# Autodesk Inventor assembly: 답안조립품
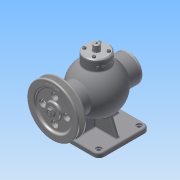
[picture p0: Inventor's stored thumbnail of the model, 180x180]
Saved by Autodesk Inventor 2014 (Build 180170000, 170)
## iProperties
Created: 2017-01
Part Number: 답안조립품
Document SubType Name: Assembly
Designer: ksu
Author: ksu
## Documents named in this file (19)
- C:\Users\ksu\Desktop\470118V1013\답안조립품.iam
- C:\Users\ksu\Desktop\470118V1013\본체.ipt
- C:\Users\ksu\Desktop\470118V1013\470118V1013\V-벨트풀리.ipt
- C:\Users\ksu\Desktop\470118V1013\470118V1013\너트 M8.ipt
- C:\Users\ksu\Desktop\470118V1013\470118V1013\뒤커버.ipt
- C:\Users\ksu\Desktop\470118V1013\470118V1013\멈춤링- 15 x 1.ipt
- C:\Users\ksu\Desktop\470118V1013\470118V1013\멈춤링- 35x1.6.ipt
- KS B 1336 - 35x1.6.ipt
- C:\Users\ksu\Desktop\470118V1013\470118V1013\베어링- 6202.ipt
- KS B 2023 - 6202 - 15 x 35 x 11 - 7.8.ipt
- C:\Users\ksu\Desktop\470118V1013\470118V1013\볼트 M4 x 12.ipt
- C:\Users\ksu\Desktop\470118V1013\470118V1013\볼트 M4 x 16.ipt
- C:\Users\ksu\Desktop\470118V1013\470118V1013\부시.ipt
- C:\Users\ksu\Desktop\470118V1013\470118V1013\상부커버.ipt
- C:\Users\ksu\Desktop\470118V1013\470118V1013\슬라이드.ipt
- C:\Users\ksu\Desktop\470118V1013\470118V1013\앞커버.ipt
- C:\Users\ksu\Desktop\470118V1013\470118V1013\오일실 15 30 7.ipt
- C:\Users\ksu\Desktop\470118V1013\470118V1013\키 4 x 4 x 12.ipt
- C:\Users\ksu\Desktop\470118V1013\470118V1013\편심축.ipt
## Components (16 placed, 5 different names)
1. V-벨트풀리:1 — Mate:10, Mate:11, Mate:12
2. KS B 1336 - 35x1.6:1 — Mate:21, Mate:22
3. KS B 2023 - 6202 - 15 x 35 x 11 - 7.8:1 — Mate:3, Mate:4, Mate:6
4. KS B 2023 - 6202 - 15 x 35 x 11 - 7.8:2 — Mate:21, Mate:22, Mate:23, Mate:24, Mate:25, Mate:26, Mate:27
5. ISO 4762 M4 x 16:1 — Mate:19, Mate:20
6. ISO 4762 M4 x 16:2
7. ISO 4762 M4 x 16:3
8. ISO 4762 M4 x 16:4
9. ISO 4762 M4 x 16:5 — Mate:29, Mate:30
10. ISO 4762 M4 x 16:6
11. ISO 4762 M4 x 16:7
12. ISO 4762 M4 x 16:8
13. KS B 1021 - 에 따름 ISO 1207 - 미터 A  M 4 x 12:1 — Mate:33, Mate:34
14. KS B 1021 - 에 따름 ISO 1207 - 미터 A  M 4 x 12:2
15. KS B 1021 - 에 따름 ISO 1207 - 미터 A  M 4 x 12:3
16. KS B 1021 - 에 따름 ISO 1207 - 미터 A  M 4 x 12:4
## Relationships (19: Mate 19)
- Mate:3: KS B 2023 - 6202 - 15 x 35 x 11 - 7.8:1
- Mate:4: KS B 2023 - 6202 - 15 x 35 x 11 - 7.8:1
- Mate:6: KS B 2023 - 6202 - 15 x 35 x 11 - 7.8:1
- Mate:10: V-벨트풀리:1
- Mate:11: V-벨트풀리:1
- Mate:12: V-벨트풀리:1
- Mate:19: ISO 4762 M4 x 16:1
- Mate:20: ISO 4762 M4 x 16:1
- Mate:21: KS B 1336 - 35x1.6:1 ↔ KS B 2023 - 6202 - 15 x 35 x 11 - 7.8:2
- Mate:22: KS B 1336 - 35x1.6:1 ↔ KS B 2023 - 6202 - 15 x 35 x 11 - 7.8:2
- Mate:23: KS B 2023 - 6202 - 15 x 35 x 11 - 7.8:2
- Mate:24: KS B 2023 - 6202 - 15 x 35 x 11 - 7.8:2
- Mate:25: KS B 2023 - 6202 - 15 x 35 x 11 - 7.8:2
- Mate:26: KS B 2023 - 6202 - 15 x 35 x 11 - 7.8:2
- Mate:27: KS B 2023 - 6202 - 15 x 35 x 11 - 7.8:2
- Mate:29: ISO 4762 M4 x 16:5
- Mate:30: ISO 4762 M4 x 16:5
- Mate:33: KS B 1021 - 에 따름 ISO 1207 - 미터 A  M 4 x 12:1
- Mate:34: KS B 1021 - 에 따름 ISO 1207 - 미터 A  M 4 x 12:1
